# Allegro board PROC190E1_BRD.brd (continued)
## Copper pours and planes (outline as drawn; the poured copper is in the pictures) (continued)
VCC_5V0 on TOP: 51.07,83.34 50.44,83.34 50.39,83.29 50.39,82.98 50.44,82.93 50.44,81.25 49.75,80.57 49.75,80.37 49.9,80.21 50.92,80.21 51.25,80.54 51.25,83.16
VCC_5V0 on TOP: 43.91,158.88 43.4,158.88 43.27,158.75 40.78,158.75 40.73,158.7 39.59,158.7 39.51,158.62 39.51,158.39 39.54,158.37 40.89,158.37 41.19,158.06 41.9,158.06 42.18,157.78 43.93,157.78 43.99,157.84 43.99,158.8
VCC_5V0 on TOP: 128.57,147.37 130.98,147.37 131.26,147.66 133.35,147.66 133.35,149.42 133.28,149.49 128.66,149.49 128.55,149.38 128.55,147.39
VCC_5V0 on TOP: 25.47,31.47 12.92,31.47 11.4,29.95 11.4,24.82 14.98,24.82 14.98,24.23 26.28,24.23 26.28,26.8 25.72,27.36 25.72,31.22
VCC_5V0 on TOP: 18.43,119.05 16.02,119.05 15.74,118.76 13.65,118.76 13.65,117.01 13.69,116.97 18.43,116.97
VCC_5V0 on TOP: 37.54,57.57 36.21,57.57 36.21,57.71 34.99,57.71 34.44,57.16 34.44,56.39 35.85,56.39 35.85,57.16 37.54,57.16
VCC_5V0 on TOP: 15.51,9.53 17.39,9.53 17.39,13.06 17.87,13.54 17.87,14.58 16.98,14.58 16.27,13.87 15.66,13.87 15.51,13.72
VCC_5V0 on BOTTOM: 49.78,80.24 49.88,80.14 50.61,80.14 51.15,80.67 51.81,80.67 51.81,82.14 51.17,82.78 50.46,82.78 49.78,82.09
VCC_5V0 on BOTTOM: 92.8,31.19 91.69,31.19 91.33,30.84 91.33,27.74 91.61,27.46 92.78,27.46 93.01,27.69 93.01,30.99
VCC_5V0 on BOTTOM: 38.75,56.98 38.75,58.61 40.84,58.61 40.84,56.99 42.59,56.99 42.59,59.97 35.96,59.97 35.96,58.47 35.14,57.65 34.6,57.65 34.38,57.44 34.38,56.67 34.61,56.45 35.98,56.45 36.52,56.98
VCC_5V0 on BOTTOM: 52.2,16.72 49.41,16.72 49.41,20.17 52.2,20.17
VCC_5V0 on BOTTOM: 37.71,55.64 37.71,52.27 42.99,52.27 43.24,52.52 43.24,53.83 43.68,54.27 43.68,54.98 43.58,55.08 41.87,55.08 41.87,55.66 40.93,55.66 40.93,53.99 38.76,53.99 38.76,55.64
VCC_5V0 on BOTTOM: 12.13,31.29 12.13,25.58 26.89,25.58 26.89,31.29
VCC_5V0 on L03_SIG1: 25.98,31.39 25.34,31.39 25.16,31.22 25.16,28.17 25.29,28.04 25.75,28.04 26.08,28.37 26.08,31.29
VCC_5V0 on L03_SIG1: 17.44,7.92 18,8.48 18,25.53 19.88,27.41 23.79,27.41 24.88,28.5 24.88,31.32 24.53,31.67 13.15,31.67 12.41,30.94 12.41,8.56 13.05,7.92
VCC_5V0 on L03_SIG1: 65.75,58.98 65.22,58.98 64.28,58.04 64.28,53.62 66.06,51.84 66.36,51.84 66.5,51.7 66.5,49.97 65.32,48.79 65.32,46.33 65.91,45.75 67.38,45.75 67.86,46.23 67.86,46.66 67.48,47.04 67.15,47.04 67.15,48.82 67.56,49.23 67.56,51.84 67.15,52.25 67.15,57.58
VCC_5V0 on L04_PWR1: outline of 96 points within 13.63,13.97 135.93,175.9
VCC_CORE on TOP: 33.49,66.8 32.33,65.63 32.33,63.6 32.45,63.47 46.98,63.47 46.98,64.64 45.61,66.01 43.91,66.01 41.81,68.11 36.84,68.11 36.84,66.8
VCC_CORE on BOTTOM: 33.15,66.45 33.15,63.55 44.82,63.55 45.05,63.32 46.55,63.32 46.55,65.96 42.31,65.96 41.83,66.45
VDD_2V5 on TOP: 116.1,45.41 114.93,45.41 114.93,43.79 115.1,43.62 115.21,43.62 115.94,42.89 115.94,42 116.53,42 116.53,43.05 116.1,43.48
VDD_2V5 on TOP: 83.67,45.44 82.5,45.44 82.5,43.84 83.51,42.82 83.51,42 84.1,42 84.1,43.05 83.67,43.48
VDD_2V5 on BOTTOM: 92.86,36.11 92.86,34.15 93.02,34 93.02,32.96 93.2,32.77 96.19,32.77 96.42,33.01 96.42,36.11
VDD_2V5 on L04_PWR1: 88.69,31.52 86.56,31.52 83.61,34.47 83.61,38.38 82.06,39.93 82.06,45.62 82.72,46.28 86.61,46.28 90.62,42.27 93.59,42.27 96.74,45.42 115.71,45.42 116.17,44.96 116.17,39.22 110.1,33.15 90.31,33.15
VDD_CANUART on TOP: 51.53,79.45 51.15,79.83 50.41,79.83 50.41,78.03 50.49,77.95 50.49,77.19 50.67,77.01 51.1,77.01 51.25,77.17 51.25,77.83 51.76,78.33 52.77,78.33 53,78.11 53,76.94 53.21,76.73 54.35,76.73 54.35,79.45
VDD_CORE on TOP: 85.9,98.02 84.68,98.02 84.47,97.82 84.47,94.13 83.71,93.37 83.71,91.34 84.02,91.03 85.08,91.03 85.37,91.33 85.37,95.52 85.49,95.63 85.49,96.39 85.9,96.8
VDD_CORE on TOP: 36.76,69.9 36.76,68.68 40.99,68.68 40.99,71.68 35.63,71.68 35.63,69.9
VDD_CORE on TOP: 51.63,97.03 49.98,97.03 49.98,94.97 51.63,94.97
VDD_CORE on BOTTOM: 83.69,93.68 83.69,91.08 85.59,91.08 85.59,94.23 84.24,94.23
VDD_CORE on BOTTOM: 52.27,91.92 53.69,91.92 53.69,93.07 53.31,93.45 52.27,93.45
VDD_CORE on BOTTOM: 51.5,97.13 50.34,97.13 50.34,96.37 49.98,96.01 49.98,95.28 51.5,95.28
VDD_CORE on L04_PWR1: 28.31,73 28.34,91.6 38.52,101.78 82.77,101.78 85.59,98.96 85.59,88.62 79.34,88.62 77.97,87.25 76.83,87.25 76.17,86.59 76.17,82.37 76.67,81.86 78.61,81.86 78.78,81.69 78.78,80.92 78.53,80.67 78.02,80.67 77.41,80.06 75.86,80.06 74.9,81.03 72.23,81.03 71.65,81.61 66.57,81.61 66.29,81.89 66.29,85.04 65.8,85.52 63.75,85.52 61.56,87.71 61.56,88.62 59.68,90.5 47.36,90.5 41.47,84.61 41.47,69.37 40.91,68.81 30.47,68.81 30.02,69.27 30.02,71.3
VDD_CORE_REG_SW1 on TOP: 38.22,60.2 39.15,59.26 39.15,58.08 39.48,58.08 39.48,61.9 39.29,62.1 36.56,62.1 36.49,62.03 36.49,60.2
VDD_CORE_REG_SW2 on TOP: 41.65,60.48 40.49,59.31 40.49,58.08 40.15,58.08 40.15,61.93 40.33,62.1 43.15,62.1 43.15,60.48
VDD_MMC0 on TOP: 121.89,69.96 123.36,69.96 123.42,70.01 123.42,73.56 121.87,73.56 121.87,69.98
VDD_MMC0_SD on TOP: 132.76,76.43 131.62,76.43 131.23,76.05 131.23,74.63 131.62,74.24 132.73,74.24 132.76,74.27
VDD_MMC0_SD on TOP: 121.61,75.36 121.61,73.84 123,73.84 123,75.36
VDD_MMC0_SD on BOTTOM: 133.6,76.33 131.16,76.33 131.16,75.41 131.49,75.41 131.62,75.54 133.6,75.54
VDD_MMC0_SD on L04_PWR1: 132,76.53 131.11,76.53 130.62,76.05 130.62,75.34 129.33,74.04 124.73,74.04 123.41,75.36 121.84,75.36 121.63,75.16 121.63,73.63 122.22,73.05 130.52,73.05 132.35,74.88 132.35,76.17
VDDA1V8 on TOP: 42.14,53.62 42.14,54.51 44.19,54.51 44.34,54.66 45.1,54.66 45.48,54.28 45.48,52.93 45.64,52.78 47.19,52.78 47.62,53.21 47.62,54.12 47.78,54.28 48.9,54.28 48.96,54.22 48.96,50.6 49.57,49.99 51.25,49.99 51.5,49.73 51.5,49.02 51.33,48.84 48.33,48.84 47.64,49.53 47.64,51.55 47.27,51.92 45.43,51.92 43.73,53.62
VDDA1V8 on BOTTOM: 50.74,50.14 50.74,48.82 51.5,48.82 51.5,50.14
VDDA1V8 on L04_PWR1: 53.97,52.04 49.9,52.04 49.65,51.79 49.65,49.4 50.28,48.77 51.35,48.77 51.35,51.08 51.61,51.33 52.75,51.33 53.61,50.47 53.61,46.79 55.24,45.16 74.47,45.16 75.43,46.13 75.43,55.04 75.1,55.37 73.91,55.37 73.69,55.16 73.71,48.26 72.48,47.04 69.89,47.04 68.45,48.49 57.52,48.49
VDDA_1V8 on TOP: 51.58,54.25 51.58,52.4 51.27,52.1 51.27,51.56 51.07,51.36 49.28,51.36 49.28,54.25
VDDA_1V8 on TOP: 119.4,56.97 119.4,55.24 122.39,55.24 122.39,56.97
VDDA_1V8 on TOP: 82.11,73.03 82.44,72.69 82.44,70.61 81.78,69.95 81.78,69.01 81.96,68.83 83.46,68.83 83.94,68.35 83.94,67.67 83.36,67.08 82.9,67.08 82.62,66.8 82.62,66.14 82.82,65.94 84.07,65.94 84.55,66.42 84.55,69.22 83.2,70.56 83.2,73.13 82.95,73.38 82.95,73.71 82.69,73.96 82.21,73.96 82.11,73.86
VDDA_1V8 on BOTTOM: 68.52,78.94 67.81,78.94 67.73,78.87 67.73,78.11 67.78,78.05 67.78,77.52 67.94,77.37 68.42,77.37 68.55,77.5 68.55,78.92
VDDA_1V8 on BOTTOM: 79.01,75.26 78.05,75.26 78.02,75.23 78.02,74.63 78.05,74.6 78.91,74.6 79.21,74.3 79.21,72.9 79.52,72.59 82.31,72.59 82.59,72.87 83.63,72.87 84.22,72.29 88.1,72.29 88.31,72.09 88.31,71.3 88.38,71.22 88.99,71.22 89.04,71.27 89.04,72.36 88.59,72.82 84.8,72.82 83.66,73.96 81.73,73.96 81.75,73.99 81.75,74.22 81.7,74.27 81.15,74.27 81.02,74.14 81.02,73.15 80.97,73.1 79.95,73.1 79.82,73.23 79.82,74.45
VDDA_1V8 on BOTTOM: 118.58,56.85 118.58,55.58 121.3,55.58 121.3,56.85
VDDA_1V8 on BOTTOM: 73.65,66.62 74.34,65.94 83.46,65.94 83.74,66.22 83.74,66.9 82.85,67.79 79.47,67.79 79,67.32 74.83,67.32 74.66,67.5 74.66,68.14 74.41,68.38 73.78,68.38 73.65,68.25
VDDA_1V8 on L04_PWR1: 50.49,53.82 50.36,53.7 50.36,52.5 50.53,52.34 54.4,52.34 57.66,49.07 64.36,49.07 65.6,50.32 65.6,53.67 66.79,54.86 72.33,54.86 73.4,55.93 78.94,55.93 80.64,54.23 120.08,54.23 120.36,54.51 120.36,56.82 119.75,57.43 81.32,57.43 78.4,60.35 78.4,68.68 77.89,69.19 71.9,69.19 70.3,67.59 70.3,61.16 68.78,59.64 67.2,59.64 61.38,53.82
VDDA_1V8_FB1 on L04_PWR1: 85.03,71.3 85.03,85.12 83.53,86.61 78.76,86.61 78.12,85.98 77.49,85.98 77.06,85.55 76.57,85.55 76.57,86.79 76.7,86.92 78.1,86.92 79.34,88.16 88.05,88.16 89.04,87.17 89.04,71.3
VDDA_1V8_FB2 on L04_PWR1: 77.94,85.6 77.56,85.6 76.5,84.53 76.5,82.32 76.75,82.07 78.86,82.07 79.39,81.53 79.39,80.44 78.48,79.53 75.63,79.53 74.87,80.29 74.29,80.29 74.08,80.09 74.08,76 75.1,74.98 79.39,74.98 80.89,76.48 80.89,82.35 79.8,83.44 78,83.44 77.54,83.9 77.54,84.43 78.1,84.99 78.1,85.45
VDDA_1V8_FB3 on L03_SIG1: 72.99,81.71 72.64,81.71 72.33,81.41 72.33,65.91 73.53,65.91 73.53,81.18
VDDA_1V8_FB4 on L04_PWR1: 81.27,84.56 78.05,84.56 78.05,83.59 80.18,83.59 81.48,82.3 81.48,76.23 80.05,74.8 80.05,74.32 80.36,74.02 81.27,74.02 82.75,75.49 82.75,83.08
VDDA_1V8_FB_OSC on BOTTOM: 69.45,79.68 68.47,79.68 68.19,79.96 67.71,79.96 67.71,79.2 69.42,79.2 69.51,79.29 69.51,79.61
VDDA_ADC0 on L03_SIG1: 74.62,81.1 74.26,81.1 74.26,80.77 74.41,80.62 74.41,80.44 74.54,80.31 74.54,71.91 75.3,71.15 75.3,70.05 74.9,69.65 74.9,67.79 75.05,67.64 75.2,67.64 75.8,68.24 75.8,69.76 76.04,70 76.04,71.5 75.33,72.21 75.33,80.34 75.13,80.34 74.62,80.85
VDDA_CORE_USB on TOP: 84.07,98.15 82.64,98.15 82.64,96.27 82.78,96.13 82.78,92.65 82.9,92.53 83.28,92.53 83.46,92.71 83.46,94.13 84.07,94.74
VDDA_CORE_USB on L03_SIG1: 79.86,84.8 79.86,86.16 79.52,86.5 79.52,91.54 80.33,92.35 83.33,92.35 83.33,93.27 78.91,93.27 78.02,92.38 78.02,86.97 78.2,86.79 78.2,85.7 77.82,85.32 76.98,85.32 76.67,85.01 76.67,84.76 77.06,84.38 79.44,84.38
VDDR_CORE on TOP: 52.98,70.33 51.45,70.33 51.45,68.91 52.98,68.91
VDDR_CORE on BOTTOM: 48.45,64.38 48.45,62.18 51.27,62.18 51.27,64.38
VDDR_CORE on L03_SIG1: 74.34,82.85 74.74,82.45 77.03,82.45 77.03,84.18 76.88,84.33 76.32,84.33 76.14,84.51 76.14,85.47 76.61,85.94 77.68,85.94 77.92,86.18 77.92,86.61 77.44,87.1 77.44,88.98 77.16,89.26 75.15,89.26 74.94,89.04 74.94,87.9 74.69,87.66 73.07,87.66 71.72,86.31 70.96,86.31 70.55,86.72 70.27,86.72 69.89,87.1 67.71,87.1 67.33,86.72 64.76,86.72 64.08,86.03 64.08,84.51 64.53,84.05 68.34,84.05 68.52,84.23 73.32,84.23 73.5,84.4 73.88,84.4 74.34,83.95
VDDR_CORE on L04_PWR1: 57.04,76.15 53.21,72.31 52.62,72.31 51.53,71.22 51.53,67.89 50.69,67.06 50.69,65.13 49.32,63.75 49.32,62.69 49.88,62.13 51.43,62.13 53.43,64.14 53.43,68.5 59.53,74.6 61.16,74.6 64.94,78.38 64.94,80.44 65.88,81.38 65.88,84.84 65.65,85.06 64.18,85.06 62.83,83.72 60.16,83.72 57.04,80.59
VDDR_CORE_0V85 on BOTTOM: 46.93,65.1 46.93,65.76 47.19,66.01 51.12,66.01 51.17,65.96 51.17,64.92 51.02,64.77 48.05,64.77 47.92,64.9 47.13,64.9
VDDSHV_CANUART on TOP: 21.1,11.89 20.41,11.89 20.36,11.84 20.36,11.02 21.18,10.21 25.87,10.21 27.96,12.29 27.96,13.34 33.52,18.9 33.52,24.08 27.37,30.23 27.37,35.26 25.47,37.16 25.47,44.93 25.85,45.31 25.85,46.96 25.67,47.14 24.76,47.14 24.6,46.99 24.6,44.6 24.81,44.4 24.81,35.2 26.74,33.27 26.74,29.97 32.78,23.93 32.78,19.81 27.04,14.07 27.04,12.47 25.42,10.85 21.46,10.85 21.1,11.2
VDDSHV_CANUART on TOP: 48.38,35.89 45.46,35.89 45.26,35.69 45.26,35.23 45.43,35.05 48.35,35.05 48.58,35.28 48.58,35.69
VDDSHV_CANUART on TOP: 48.38,66.52 48.38,62.69 48.46,62.61 48.89,62.61 49.09,62.81 49.09,65.28 51.71,67.89 52.42,67.89 52.52,67.79 52.52,67.06 52.24,66.78 52.24,58.78 52.01,58.55 52.01,52.32 51.48,51.79 51.48,50.77 51.71,50.55 51.99,50.55 52.29,50.85 52.29,51.28 52.54,51.54 52.54,57.91 53.15,58.52 53.15,68.2 52.75,68.61 51.2,68.61 50.18,67.59 49.45,67.59
VDDSHV_CANUART on TOP: 23,51.66 23,53.09 22.85,53.24 22.27,53.24 22.12,53.09 22.12,51.77 22.22,51.66
VDDSHV_CANUART on TOP: 39.54,159.66 41.06,159.66 41.9,160.5 42.94,160.5 43.17,160.27 43.17,159.59 42.79,159.21 39.57,159.21 39.44,159.33 39.44,159.56
VDDSHV_CANUART on TOP: 39.59,155.78 38.91,155.78 38.75,155.63 38.75,150.88 42.23,147.4 42.74,147.4 43.07,147.73 43.07,148.29 39.69,151.66 39.69,155.68
VDDSHV_CANUART on TOP: 53.54,83.03 53.13,83.44 53.13,84.25 49.65,87.73 49.65,100.23 50.36,100.94 54.04,100.94 55.26,102.16 55.26,114.66 56.63,116.03 56.63,120.57 57.5,121.44 60.67,121.44 61.08,121.03 66.08,121.03 66.34,120.78 67.78,120.78 68.12,121.11 68.12,124.64 68.01,124.74 66.54,124.74 66.44,124.64 66.44,124.1 66.69,123.85 67.33,123.85 67.66,123.52 67.66,121.39 67.51,121.23 66.9,121.23 66.46,121.67 65.98,121.67 65.8,121.84 65.8,122.15 65.4,122.56 64.15,122.56 63.87,122.83 62.25,122.83 61.97,122.56 56.76,122.56 55.49,121.28 55.49,116.08 54.63,115.21 54.63,102.87 53.79,102.03 50.49,102.03 49.01,100.56 49.01,87.1 52.49,83.62 52.49,83.03 53.68,81.85 54.54,81.85 54.96,82.27 54.96,82.85 54.78,83.03
VDDSHV_CANUART on TOP: 19.88,63.2 22.04,63.2 22.75,62.48 22.75,61.24 21.94,60.43 20.59,60.43 20.44,60.58 20.44,60.88 20.52,60.96 21.51,60.96 21.61,61.06 21.61,62.51 21.51,62.61 19.88,62.61 19.83,62.66 19.83,63.14
VDDSHV_CANUART on TOP: 25.95,51.21 28.62,51.21 29.02,50.8 29.02,49.5 29,49.48 28.41,49.48 28.39,49.5 28.39,50.5 28.14,50.75 25.93,50.75 25.93,51.18
VDDSHV_CANUART on BOTTOM: 52.8,36.02 50.11,36.02 49.37,36.75 48.13,36.75 48,36.63 48,35.99 47.87,35.86 47.87,35.46 47.97,35.36 48.28,35.36 48.43,35.51 48.43,36.12 48.56,36.25 49.17,36.25 50.08,35.33 52.8,35.33
VDDSHV_CANUART on BOTTOM: 45.03,83.85 44.87,83.69 44.87,81.1 45,80.98 46.32,80.98 46.53,80.77 46.53,78.66 47.24,77.95 50.21,77.95 50.28,78.03 50.28,78.54 50.18,78.64 48.91,78.64 48.3,79.25 48.3,82.4 48.47,82.56 49.41,82.56 50,83.16 50.87,83.16 51.5,82.52 53.18,82.52 53.33,82.37 53.33,80.82 53.54,80.62 55.36,80.62 55.47,80.72 55.47,81.28 55.29,81.46 55.29,83.54 54.98,83.85
VDDSHV_CANUART on BOTTOM: 19.19,63.25 17.39,63.25 17.16,63.02 17.16,62.03 17.39,61.8 18.84,61.8 19.12,62.08 19.98,62.08 20.36,61.7 20.36,60.48 21.68,59.16 21.68,53.39 22.45,52.63 26.41,52.63 27.22,51.82 27.22,48.44 24.76,45.97 24.76,45.49 25.04,45.21 25.44,45.21 28.67,48.44 28.67,51.77 26.89,53.54 24.3,53.54 22.78,55.07 22.78,60.63 20.52,62.89 20.52,66.4 22.93,68.81 30.35,68.81 31.49,69.95 34.94,69.95 37.3,67.59 42.28,67.59 42.87,67.01 47.39,67.01 48.15,66.24 50.06,66.24 50.16,66.34 50.16,66.88 49.94,67.09 48.16,67.09 47.41,67.84 42.82,67.84 42.49,68.17 37.89,68.17 35.4,70.66 31.26,70.66 30.19,69.6 22.62,69.6 19.8,66.78 19.8,63.86
VDDSHV_CANUART on BOTTOM: 45.08,160.45 41.6,160.45 41.11,159.97 41.11,159.36 41.39,159.08 44.92,159.08 45.08,159.23
VDDSHV_CANUART on BOTTOM: 46.53,35.81 44.39,35.81 43.99,35.41 43.99,33.45 44.54,32.89 46.55,32.89 46.6,32.84 47.8,32.84 47.8,33.07 47.74,33.12 46.75,33.12 46.55,33.32 46.55,33.45 46.53,33.48 44.92,33.48 44.59,33.81 44.59,34.92 44.9,35.23 45.94,35.23 46.02,35.31 46.55,35.31 46.6,35.36 46.6,35.74
VDDSHV_CANUART on L03_SIG1: 38.47,156.29 38.47,155.4 38.88,154.99 39.95,154.99 42.79,157.84 42.79,159.59 42.04,160.34 40.84,160.34 40.03,159.53 40.03,157.84
VDDSHV_CANUART on L04_PWR1: 50.34,78.84 49.17,78.84 48.86,78.54 48.86,77.01 49.8,76.07 49.8,71.96 48.4,70.56 48.4,66.12 48.79,65.74 49.6,65.74 50.08,66.22 50.08,67.41 51.02,68.35 51.02,71.63 52.24,72.85 53,72.85 56.48,76.33 56.48,82.27 55.59,83.16 53.54,83.16 53.08,82.7 53.08,81.89 54.4,80.57 54.4,77.17 54.04,76.81 51.68,76.81 50.49,78 50.49,78.69
VDDSHV_CANUART on L04_PWR1: 43.22,148.29 42.64,148.29 41.29,146.94 41.29,128.96 44.7,125.55 56.15,125.55 59.56,122.15 62.6,122.15 62.76,122.3 62.76,124.61 60.34,127.03 44.98,127.03 42.61,129.39 42.61,146.41 43.68,147.47 43.68,147.83
VDDSHV_CANUART on L04_PWR1: 51.57,50.84 51.57,50.58 51.68,50.47 51.68,48.41 50.97,47.7 50.97,35.31 51.25,35.03 52.47,35.03 52.8,35.36 52.8,38.4 53.26,38.86 53.26,46.15 52.9,46.51 52.9,50.44 52.34,51 51.73,51
VDDSHV_SDIO on TOP: 44.52,56.47 45.21,56.47 45.41,56.26 45.41,55.12 45.26,54.97 44.16,54.97 43.89,55.25 43.89,55.5 44.29,55.91 44.29,56.24
VDDSHV_SDIO on BOTTOM: 45.56,57.28 44.37,57.28 44.37,55.52 44.8,55.09 45.56,55.09
(no net) on TOP: 11.02,1.02 11.02,175.98 135.98,175.98 135.98,1.02 ; 259 cut-outs
(no net) on BOTTOM: 11.02,1.02 11.02,175.98 135.98,175.98 135.98,1.02 ; 247 cut-outs
(no net) on L03_SIG1: 11.02,1.02 11.02,175.98 135.98,175.98 135.98,1.02 ; 231 cut-outs
ADC0_REFN on BOTTOM: 73.91,75.97 73.47,75.97 73.32,75.82 73.32,75.56 73.63,75.26 73.63,72.92 73.7,72.85 74.29,72.85 74.36,72.92 74.36,73.74 74.21,73.89 74.21,75.67
ADC0_REFP on BOTTOM: 73.37,75.31 72.99,75.31 72.61,74.93 72.61,73.69 72.76,73.53 73.3,73.53 73.45,73.69 73.45,75.23
DRAIN1 on TOP: 37.33,19.41 37.33,17.43 39.84,17.43 39.84,19.41
DRAIN1 on BOTTOM: 35.82,16.96 35.82,17.62 36.1,17.9 37.07,17.9 37.19,18.02 37.19,19.22 36.35,19.22 36.35,19.5 39.83,19.5 39.83,17.77 39.68,17.62 37.27,17.62 37.17,17.51 36.66,17.51 36.58,17.44 36.58,16.96
DRAIN2 on TOP: 40.25,19.41 40.25,17.43 43.07,17.43 43.07,19.41
DRAIN2 on BOTTOM: 43.68,16.96 43.5,17.14 43.5,17.44 43.42,17.51 43.08,17.51 42.98,17.62 40.4,17.62 40.25,17.77 40.25,19.5 43.77,19.5 43.77,19.22 42.93,19.22 42.89,19.17 42.89,17.95 43.93,17.95 44.26,17.62 44.26,17.04 44.18,16.96 ; 1 cut-out
FT4232_USB_VBUS on TOP: 65.07,4.97 65.07,6.96 64.14,7.89 64.14,8.46 60.29,8.46 59.79,8.97 59.44,8.97 59.41,8.94 59.41,8.24 58.7,8.24 58.61,8.33 58.61,8.94 58.51,9.03 58.05,9.03 57.91,8.9 57.91,7.42 58.02,7.3 62.98,7.3 63.56,6.72 63.56,5.7 64.3,4.97
LM61460_BOOT on TOP: 14.04,14.66 14.04,14.22 15.99,14.22 16.68,14.91 17.59,14.91 17.59,15.14 16.78,15.14 16.3,14.66
LM61460_FB on TOP: 19.55,14.68 19.14,14.68 19.14,13.44 19.6,12.98 19.6,11.66 19.14,11.2 17.9,11.2 17.9,10.34 19.98,10.34 20.16,10.16 20.16,9.7 20.52,9.35 21.61,9.35 21.61,9.91 21.02,9.91 19.98,10.95 19.98,13.23 19.55,13.67
LM61460_SW on TOP: 19.4,15.75 18.25,15.75 18.25,20.19 17.67,20.78 15.92,20.78 15.28,21.41 15.28,23.32 15.69,23.72 22.98,23.72 23.33,23.37 23.33,21.79 22.73,21.18 20.85,21.18 19.4,19.74
MIC1_BIAS on TOP: 80.38,171.58 76.12,171.58 75.53,170.99 75.15,170.99 74.38,170.22 74.38,170.09 74.59,169.88 75.02,169.88 75.84,170.69 79.47,170.69 80.89,169.27 80.89,165.13 80.31,164.54 80.31,160.05 78.55,158.29 78.55,155.91 77.16,154.51 77.16,147.83 78.5,146.48 79.32,146.48 79.49,146.66 79.49,147.04 79.32,147.22 78.96,147.22 77.79,148.39 77.79,153.95 79.42,155.57 79.42,157.53 81.78,159.89 81.78,170.18
MIC1_BIAS on TOP: 69,163.4 75.63,163.4 75.89,163.65 75.89,164.11 75.74,164.26 68.85,164.26 68.75,164.16 68.75,163.65
MIC1_BIAS on BOTTOM: 69.26,170.69 80.18,170.69 81.12,169.75 81.12,163.98 79.44,162.31 72.23,162.31 71.16,163.37 71.16,164.21 71.39,164.44 72.56,164.44 73.65,163.35 78.1,163.35 79.52,164.77 79.52,168.35 78.17,169.7 75.86,169.7 75.23,169.06 69.31,169.06 69.26,169.11
MIC1_BIAS on BOTTOM: 68.03,146.74 68.03,144.86 67.95,144.77 66.52,144.77 66.29,145 66.29,146.99 67.56,148.26 72.59,148.26 73.65,147.19 79.47,147.19 79.65,147.02 79.65,146.53 79.24,146.13 73.17,146.13 72.14,147.15 68.45,147.15
MIC2_BIAS on TOP: 51.81,163.45 58.49,163.45 58.74,163.7 58.74,164.24 58.49,164.49 51.81,164.49 51.55,164.24 51.55,163.7
MIC2_BIAS on TOP: 52.88,150.37 52.88,151.41 52.67,151.61 52.67,151.99 52.77,152.1 53.21,152.1 53.36,151.94 53.36,150.44 53.28,150.37
MIC2_BIAS on BOTTOM: 61.66,170.79 52.04,170.79 51.83,170.59 51.83,169.42 52.14,169.11 58.29,169.11 58.79,169.62 60.57,169.62 62.65,167.54 62.65,165.68 61.51,164.54 59.63,164.54 58.46,163.37 55.69,163.37 54.81,164.26 54.37,164.26 54.2,164.08 54.2,163.19 54.75,162.64 60.14,162.64 60.99,163.49 61.98,163.49 63.82,165.33 63.82,168.63
MIC2_BIAS on BOTTOM: 51.79,153.25 53.59,153.25 53.72,153.12 53.72,151.89 53.15,151.31 52.11,151.31 51.76,151.67 51.76,153.22
MIC2_BIAS on L03_SIG1: 53.92,160.55 52.39,159.03 52.39,151.66 52.8,151.26 53.05,151.26 53.56,151.76 53.56,158.6 55.34,160.38 55.34,164.11 55.11,164.34 55.11,165.71 58.39,168.99 58.39,170.23 58.01,170.61 55.14,170.61 53.92,169.39
PCM1_BSTOUT on TOP: 67.68,143.7 67.68,145.58 67.08,145.58 67.08,146 66.2,146 66.14,145.94 66.14,145.88 66.13,145.87 67.06,144.94 67.06,144.63 67.11,144.58 67.11,143.71 67.68,143.71
SOC_DVDD1V8 on TOP: 39.05,42.01 39.05,43.55 34.38,43.55 34.38,42.01
SOC_DVDD1V8 on L03_SIG1: 73.63,80.62 73.47,80.77 73.47,81.66 73.17,81.97 72.03,81.97 71.87,82.12 71.87,82.68 71.59,82.96 71.01,82.96 70.53,82.47 64.31,82.47 63.57,83.21 62.73,83.21 61.69,84.25 61.69,88.27 62.8,89.37 70.64,89.37 71.06,89.79 71.06,91.26 71.42,91.62 73.47,91.62 73.8,91.29 73.8,90.7 74.74,89.76 74.74,87.83 72.84,87.83 71.62,86.61 70.78,86.61 70.25,87.15 63.92,87.15 63.19,86.41 63.19,84.45 63.95,83.69 70.83,83.69 71.16,84.02 72.94,84.02 73.86,83.11 73.86,82.17 74.19,81.84 75.81,81.84 76.34,81.31 76.34,80.82 76.19,80.67 75.3,80.67 74.67,81.31 74.19,81.31 74.06,81.18 74.06,80.85 73.83,80.62
SOC_DVDD1V8 on L04_PWR1: 30.07,51.26 33.93,47.4 33.93,42.8 34.05,42.67 35.25,42.67 35.5,42.93 35.5,50.27 33.11,52.65 33.11,57.23 41.01,65.13 41.8,65.13 44.52,67.84 44.52,82.65 48.96,87.1 59.23,87.1 62.08,84.24 62.62,84.24 63.26,84.89 63.26,85.24 61.03,87.48 61.03,88.39 59.43,89.99 47.62,89.99 42.03,84.4 42.03,69.19 41.01,68.17 31.08,68.17 30.07,67.16
SOC_DVDD3V3 on TOP: 52.85,52.27 52.85,57.48 54.42,57.48 54.42,52.27
SOC_DVDD3V3 on L04_PWR1: 83.2,83.41 81.45,85.17 78.73,85.17 78.35,85.55 78.35,85.72 78.86,86.23 83,86.23 84.55,84.68 84.55,71.5 83.02,69.98 71.65,69.98 69.54,67.87 69.54,61.06 68.7,60.22 64.66,60.22 59.63,55.19 56.63,55.19 56.41,54.97 52.93,54.97 52.7,55.19 52.7,56.16 52.93,56.39 55.16,56.39 62.2,63.42 66.85,63.42 67.94,64.52 67.94,69.93 68.32,70.31 68.32,77.27 70.35,79.3 71.87,79.3 72.43,79.86 72.43,80.01 72.69,80.26 73.25,80.26 73.55,79.96 73.55,75.46 75.76,73.25 82.11,73.25 83.2,74.35
SOC_DVDD3V3_FB1 on BOTTOM: 78.83,83.95 78.83,83.31 81.45,83.31 82.29,84.15 82.29,85.22 80.41,85.22 80.41,84.07 80.28,83.95
SOC_VDD_CANUART on TOP: 61.64,79.35 61.74,79.25 61.74,78.71 57.02,78.71 56.2,77.9 56.2,76.73 54.78,76.73 54.7,76.81 54.7,79.22 54.83,79.35
SOC_VDD_CANUART on L03_SIG1: 71.93,81.28 71.42,81.28 69.13,78.99 62.68,78.99 62.22,79.45 61.26,79.45 60.98,79.17 60.98,78.28 61.41,77.85 69.84,77.85 70.17,78.18 70.17,79.2 71.37,80.39 71.93,80.39
SOC_VDDSHV5_SDIO on L03_SIG1: 79.16,84.2 78.25,84.2 78.15,84.1 78.15,82.4 76.93,81.18 76.93,80.85 76.27,80.19 76.27,74.98 77.28,73.96 77.87,73.96 78.12,74.22 78.12,74.93 77.51,75.54 77.51,79.68 79.49,81.66 79.49,83.87
SOC_VDDSHV_CANUART on BOTTOM: 63.64,82.65 63.29,82.65 63.01,82.37 60.8,82.37 60.11,81.69 57.62,81.69 57.02,82.3 57.02,82.75 57.55,83.29 57.55,84.66 56.44,85.76 45.13,85.76 43.27,83.91 43.27,81.1 43.38,81 44.47,81 44.62,81.15 44.62,83.92 44.92,84.23 55.11,84.23 55.59,83.74 55.59,81.51 57.02,80.09 60.01,80.09 61.77,81.84 63.29,81.84 63.77,82.32 63.77,82.52
SOC_VDDSHV_CANUART on L03_SIG1: 71.44,82.65 71.16,82.65 70.66,82.14 64.18,82.14 63.67,82.65 63.14,82.65 62.7,82.22 62.7,81.79 63.52,80.98 64.61,80.98 64.97,80.62 68.27,80.62 68.7,81.05 70.76,81.05 70.96,81.25 70.96,81.76 71.57,82.37 71.57,82.52
SW_2V5 on BOTTOM: 93.09,31.65 91.62,31.65 91.62,31.44 92.94,31.44 93.43,30.96 95.6,30.96 95.6,32.21 93.65,32.21
UART_SHIELD on TOP, BOTTOM, L02_GND1, L03_SIG1, L04_PWR1, L05_GND2: 72.59,3.78 72.59,1.36 72.25,1.02 61.87,1.02 61.67,1.21 61.67,6.35 62.08,6.76 62.79,6.76 63.18,6.37 63.18,4.99 63.08,4.89 63.08,3.96 63.46,3.58 68.84,3.58 69.34,4.08 69.34,4.66 69.17,4.82 69.17,6.34 69.54,6.71 70.26,6.71 71.32,5.64 71.32,4.59 71.75,4.16 72.2,4.16
USB_TYPEC1_EARTH on TOP, BOTTOM, L02_GND1, L03_SIG1, L04_PWR1, L05_GND2: 40.23,1.02 27,1.02 27,8.23 30.29,8.23 30.55,7.98 30.55,4.27 31.06,3.77 37.76,3.77 38.21,4.23 38.21,7.94 38.51,8.23 40.23,8.23
USB_TYPEC2_EARTH on TOP, BOTTOM, L02_GND1, L03_SIG1, L04_PWR1, L05_GND2: 55.23,1.02 42,1.02 42,8.23 45.29,8.23 45.55,7.98 45.55,4.27 46.06,3.77 52.76,3.77 53.21,4.23 53.21,7.94 53.51,8.23 55.23,8.23
VMAIN on TOP: 38.32,160.25 37.99,160.25 37.84,160.1 37.84,159.89 37.61,159.66 36.52,159.66 36.52,159.33 37.66,159.33 37.84,159.16 37.84,158.88 37.99,158.72 38.35,158.72 38.42,158.8 38.42,160.15
VMAIN on TOP: 29.76,20.65 26.41,20.65 25.72,19.96 25.72,18.67 25.44,18.39 23.87,18.39 23.03,17.55 21.33,17.55 20.82,17.04 19.7,17.04 19.7,16.13 19.86,15.98 27.7,15.98 28.75,17.02 28.75,18.21 29.13,18.59 29.13,19.43 29.76,20.07
VMAIN on TOP: 17.87,17.17 15.13,17.17 14.65,17.65 12.44,17.65 12.44,15.98 14.24,15.98 14.47,16.21 15.82,16.21 16.02,16.41 17.87,16.41
VMAIN on BOTTOM: 38.52,160.2 38.07,160.2 37.61,159.74 36.82,159.74 36.72,159.64 36.72,158.98 37,158.7 38.45,158.7 38.52,158.78
VMAIN on BOTTOM: 12.74,17.5 12.74,14.96 19.32,14.96 19.32,17.5
VMAIN on BOTTOM: 28.29,20.9 24.5,20.9 24.5,16.81 28.29,16.81
VMAIN on L04_PWR1: 27.63,20.17 23.44,20.17 20.21,23.39 20.21,44.53 15.33,49.4 15.33,103.43 13.07,105.69 13.07,138.91 29.71,155.55 35.73,155.55 39.03,158.85 39.03,166.17 38.19,167 19.3,167 11.24,158.95 11.24,16.43 12.92,14.76 27.17,14.76 27.63,15.21
VMAIN_PD on TOP: 28.97,24.75 26.97,24.75 26.97,22.96 27.06,22.87 27.59,22.87 28.26,22.2 29.51,22.2 29.51,23.28 29,23.79 29,24.72
VMAIN_PD on TOP: 42.54,14.01 42.54,16.25 42.67,16.38 44.7,16.38 44.83,16.26 44.83,15.7 45.24,15.28 45.24,14.01
VMAIN_PD on TOP: 37.45,13.84 37.45,14.86 37.88,15.29 37.88,16.31 37.93,16.36 38.77,16.36 38.82,16.31 38.82,14.97 38.66,14.81 38.66,13.84
VMAIN_PD on BOTTOM: 42.13,16.59 42.13,17.41 42.82,17.41 43.6,16.64 44.41,16.64 44.59,16.46 44.59,15.57 44.41,15.39 42.68,15.39 42.53,15.54 42.53,16.19
VMAIN_PD on BOTTOM: 38.85,17.48 38.12,17.48 38.09,17.45 38.09,16.43 37.89,16.23 37.89,14.99 37.94,14.94 38.78,14.94 38.85,15.01
VMAIN_PD on L03_SIG1: 44.82,16.94 42.38,16.94 42.31,16.87 42.31,15.42 41.7,14.81 39.64,14.81 38.98,15.47 38.98,16.64 35.96,16.64 35.55,16.23 32.96,16.23 32.35,16.84 32.35,22.63 32.81,23.09 32.81,24.49 32.56,24.74 23.51,24.74 22.9,24.13 22.9,12.88 24.38,11.4 35.07,11.4 35.96,10.52 43.4,10.52 44.82,11.94
VPP_1V8 on TOP: 63.64,66.19 64.36,66.19 64.58,65.96 65.83,65.96 66.06,65.74 66.06,65.43 65.7,65.07 63.67,65.07 63.64,65.1
VPP_1V8 on L03_SIG1: 70.63,79.17 70.63,78.21 69.56,77.14 69.56,71.12 65.58,67.13 65.58,65.56 65.7,65.43 66.21,65.43 66.77,65.99 66.77,67.06 71.16,71.45 71.16,76.99 71.9,77.72 71.9,79.53 72.1,79.73 72.1,80.09 71.7,80.09 71.65,80.04 71.65,79.93 71.42,79.71 71.16,79.71
VPP_SUPPLY on TOP: 61.94,61.82 61.08,61.82 61.05,61.85 61.05,63.02 61.59,63.55 61.59,66.14 61.69,66.24 62.86,66.24 63.01,66.09 63.01,65.2 62.73,64.92 62.25,64.92 62.12,64.8 62.12,62.71 61.94,62.53
XDS_SHIELD on TOP, BOTTOM, L02_GND1, L03_SIG1, L05_GND2: 11.06,45.29 16.48,45.29 16.89,45.7 16.89,46.83 16.54,47.17 15.06,47.17 14.82,46.93 14.14,46.93 13.78,47.28 13.78,52.72 14.08,53.02 14.9,53.02 14.96,52.96 16.31,52.96 16.75,53.39 16.75,54.11 16.29,54.57 11.06,54.57
XDS_SHIELD on BOTTOM: 14.84,58.7 14.85,58.69 14.85,55.4 14.87,55.38 14.87,54.57 16.29,54.57 16.75,54.11 16.75,53.39 16.31,52.96 14.96,52.96 14.9,53.02 14.08,53.02 13.78,52.72 13.78,47.28 14.14,46.93 14.82,46.93 15.06,47.17 16.54,47.17 16.89,46.83 16.89,45.7 16.48,45.29 11.02,45.29 11.02,58.02 11.7,58.7
XDS_USB_VBUS on TOP: 15,51.03 16.35,51.03 17.16,51.84 18.48,51.84 18.99,51.33 18.99,50.6 19.07,50.52 20.26,50.52 20.72,50.98 20.72,52.58 20.69,52.6 15.31,52.6 15,52.3
XDS_USB_VBUS on TOP: 28.8,76.07 28.8,75.03 28.85,74.98 30.32,74.98 30.62,74.68 30.62,74.17 31.47,74.17 31.41,74.23 31.41,75.77 30.22,75.77 29.68,76.3 29.02,76.3
XDS_USB_VBUS on BOTTOM: 19.93,50.7 19.32,51.31 19.32,57.51 12.03,64.8 12.03,72.59 12.84,73.41 20.87,73.41 22.67,75.21 31.46,75.21 31.46,73.48 29.86,73.48 28.85,72.47 28.85,71.6 21.56,71.6 21.02,72.14 14.9,72.14 13.96,71.2 13.96,64.64 21.07,57.53 21.07,50.88 20.9,50.7
XDS_USB_VBUS on BOTTOM: 28.01,82.73 27.42,82.73 27.2,82.5 27.2,80.82 28.08,79.93 30.57,79.93 30.78,80.14 30.78,80.47 30.52,80.72 28.52,80.72 28.08,81.15 28.08,82.65
N24605846 on TOP: 65.49,146.36 65.49,143 66.82,143 66.82,144.81 65.96,145.67 65.96,147.39 65.5,147.39 65.5,146.36
N25809420 on TOP: 82.13,42.98 82.87,42.24 82.87,38.69 82.97,38.58 82.97,36.32 83.63,35.66 91.15,35.66 92.75,37.26 92.75,38.68 92.75,38.69 92.75,42.59 93.13,42.98 95.32,42.98 95.32,36.73 92.52,33.93 82.03,33.93 80.59,35.38 80.59,42.98
N25809420 on BOTTOM: 93.11,41.26 96.09,41.26 96.09,38.64 93.21,38.64 93.21,40.46 92.94,40.73 92.94,41.08
N25815350 on TOP: 114.62,43.2 115.3,42.53 115.3,38.14 114.19,37.03 114.19,35 115.28,33.91 123.28,33.91 125.18,35.8 125.18,42.68 125.56,43.07 127.93,43.07 127.93,36.02 124.45,32.54 114.57,32.54 112.54,34.57 112.54,43.2
N25815350 on BOTTOM: 112.88,41.26 114.96,41.26 115.1,41.13 115.1,40.29 114.72,39.91 114.72,38.71 114.59,38.58 113.03,38.58 112.8,38.81 112.8,39.5 112.65,39.65 112.65,41.03
N27162147 on BOTTOM: 53.1,14.24 53.1,15.53 53.27,15.7 55.53,15.7 55.53,18.23 52.54,18.23 52.51,18.21 52.51,14.24
N27162183 on TOP: 51.01,15.7 51.01,13.92 56.05,13.92 56.05,15.7
N27162183 on BOTTOM: 49.84,15.4 49.84,16.44 52.09,16.44 52.21,16.32 52.21,14 50.96,14 50.96,14.46 50.02,15.4
N27162293 on BOTTOM: 49.53,15.28 49.53,16.36 46.43,16.36 46.43,15.37 46.53,15.28
N27175987 on TOP: 91.03,57.52 92.42,57.52 92.72,57.22 93.43,57.22 93.6,57.39 93.6,59.79 93.47,59.92 92.89,59.92 92.85,59.88 92.85,58.65 92.51,58.31 91.07,58.31 91.01,58.25 91.01,57.54
N27224561 on TOP: 53.83,150.41 53.83,151.36 53.92,151.44 53.92,152.2 52.82,153.29 52.82,154.84 54.37,154.84 54.37,150.39 53.85,150.39 53.85,150.41

Small or netless copper shapes (teardrops, artwork), in the pictures only: 18 on TOP, 21 on BOTTOM, 19 on L03_SIG1

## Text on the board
Ref Des/Assembly Bottom: A | BOTTOM  ASSEMBLY OF PROC190E1
Ref Des/Silkscreen Bottom: A | uSD_CONN | ASSY# | FOR EVALUATION ONLY; | NOT FCC APPROVED FOR RESALE
User.Comments: BOARD NAME: | AM275 EVM | REV: E1 | DATE: 16/08/24 | DESCRIPTION: | SHEET | OF | 13 | PROC190E1 | SCALE: 1 | TEXAS INSTRUMENTS
Ref Des/Assembly Top: TOP ASSEMBLY OF PROC190E1
Ref Des/Silkscreen Top: JTAG_CONN | VCC3V3_XDS | AEC2 | SOC_DVDD1V8 | CAN_WKUP_HDR | INT | DGND | VDD_CORE | VBUS_TYPEC1 | WAIT-IN-RESET | PMIC_CORE_CONFIG | MCU_RESETz | VDDR_CORE_PWR_LED | VCC_3V3_SYS_PWR_LED | SOC_VDDSHV_CANUART | CORE_CONFIG | PMIC_RSTOUT_LED | MCU WARM RST | SOC_DVDD3V3 | PMIC_RSTOUT | LINE_IN_2 | VCC_5V0 | VPP_1V8 | UART_CONN | BOOTMODEON_HDR | LINE_IN_1 | LINE_OUT_1 | RESETSTATZ_1V8 | ETHO_CONN | MCU_PORZ_HDR | PORz | LINE_OUT_2 | MMC0_SEL | MLB_HDR | VDD_2V5 | ADC_REFP_VSEL | ETH1_CONN | AEC1 | VDD_MMC0_SD | ADC0_HDR | PMIC_LPM_SEL | PD_PGM | USB-C PWR | MCAN0_HDR | VBUS_TYPEC1_PWR_LED | XDS_USB_VBUS | PWR ERROR | INDICATION LED | JTAG_CTI | VBUS_TYPEC2_PWR | EEPROM_WP_HDR | FT_PWREN#_LED | VBUS_TYPEC2 | VDDA_1V8 | VDDR_CORE | USB-C DRP | IO RET WAKE | SOC_VDD_CANUART | VBAT_IN | BMODE 0-7 | SoC_GPIO_LED | IO EXP GPIO LED | BMODE 8-15 | MLB_VSEL_HDR | AUDIO-AM275-EVM | PROC190E1 | AM275 EVM | SL# | OPN#
PAGE_OUTLINE: REVIEWED BY | APPROVED BY | LAYOUT BY | SIGNATURES | BINDU | SATHEESH | PANDI | 160824 | DATE | SIZE | SCALE: | D | NONE | SHEET 1 OF 23 | PROC190E1 | Rev | E1 | TEXAS INSTRUMENTS | AM275 EVM
DISPLAY_TOP: 16. | 17. | ENSURE UL REGISTERED E-FILE NUMBER SHALL BE PRINTED ON THE PCB SILKSCREEN. | VIA ON PAD SHALL BE TYPE-VI FILLED.
User.12: R33 | C26 | H3 | H4 | R21 | R22 | R24 | R25 | R27 | R28 | R30 | J40 | R31 | R15 | R13 | R16 | R14 | R3 | R1 | R4 | R2 | R18 | C23 | C22 | R17 | C17 | R19 | C24 | C25 | R20 | R23 | R26 | R29 | R32 | 8
User.13: ASSEMBLY_BOTTOM | BOTTOM ASSEMBLY OF PROC167A
User.15: SECONDARY-SIDE-SIG | 11
User.16: BOARD NAME: | AM62D EVM  BOARD | REV: E1 | DATE: 29/04/24 | DESCRIPTION: | SHEET | OF | 15 | PROC180E1 | SCALE: 1 | TEXAS INSTRUMENTS
User.18: J1 | R75 | R30 | C73 | C104 | C110 | C52 | C109 | C51 | C46 | C114 | C56 | C15 | C25 | C83 | LBL1 | TP28 | TP7 | TP8 | TP24 | TP12 | TP23 | TP18 | TP2 | TP25 | TP19 | C47 | C105 | TP17 | TP1 | TP3 | TP11 | C68 | C10 | C54 | C76 | C18 | C75 | C17 | C80 | C22 | C77 | C74 | C16 | C19 | R36 | R81 | R79 | R34 | R31 | R26 | R76 | R71 | C14 | C7 | C72 | C65 | C112 | C23 | C94 | C36 | C81 | C69 | C55 | C11 | C113 | C82 | C24 | C37 | C95 | Bottom Overlay | Bottom Solder | M1 Board Outline | TEXAS INSTRUMENTS | Not in version control | SVN REV: | .PCB_Rev | 15:44:36 | REV: | 22-07-2024 | .PRJ_Number | GENERATED    : | BOARD #: | .VariantName | Plot_File_Name is not interpreted until output | ASSEMBLY VARIANT: | COMPONENTS MARKED 'DNP' SHOULD NOT BE POPULATED. | PCB VIEWED FROM BOTTOM SIDE | PLOT NAME = | For evaluation only; not FCC approved for resale.
User.19: 80 | 2 | 79
User.45: 03 | 04 | 05 | STRIPLINE | MICROSTRIP | EDGE COUPLED STRIPLINE | EDGE COUPLED MICROSTRIP | L1 | L3 | L1,L6 | 5.8 | 5 | 3.7 | 4.2 | 3.6 | 6 | 4.4 | 8 | NA | 120 | 90 | 50 | L2 | L2,L5 | FIGURE | SIZE | 8.0 | 36.0 | 40.0 | 44.0 | 60.0 | 32.0 | 108.0 | 126.0 | 48.0x22.0 | 62.0x24.0 | 68.0x34.0 | 82.0x24.0 | 158.0x78.0 | DRILL CHART: TOP to BOTTOM | ALL UNITS ARE IN MILS | TOLERANCE | +3.0/-3.0 | +3.0/-2.0 | +2.0/-2.0 | PLATED | NON-PLATED | QTY | 2888 | 3 | 12 | 27 | 11 | 24 | 34 | 4 | 9 | 2 | REV # | SCALE:NONE | DESCRIPTION | FILE NAME: | REVISIONS | CCN # | DRAWING NO. | DDMMYY | DATE | OF | REV | SHEET | 01 | 02 | D | FY10XXXX5200X0X | *
